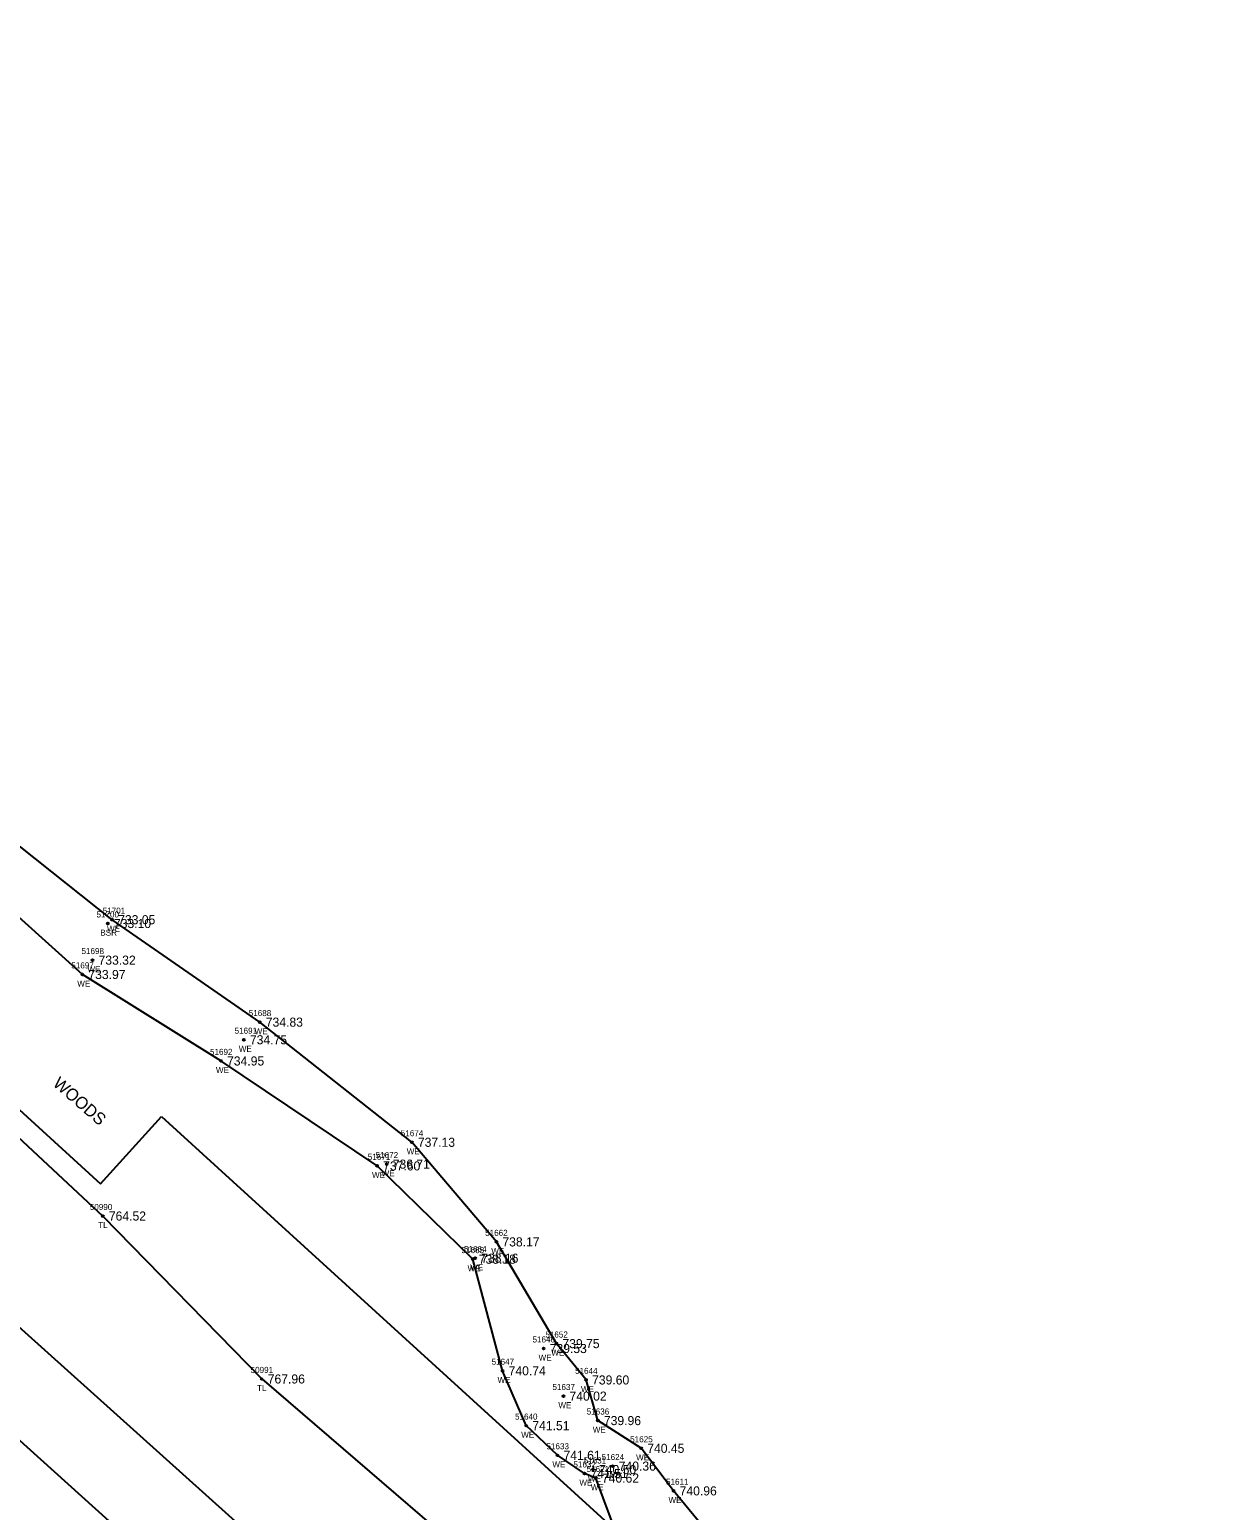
# Model space of a CAD drawing. Extents: x 1378245 to 1381654, y 996521 to 1000567.
# Drawn here: x 1379803.9 to 1379999.9, y 998853.4 to 999097.9 of the extents above; entities that cross this region are included whole.
import ezdxf

# ---------------------------------------------------------------- set-up
doc = ezdxf.new("R2010")
doc.units = 0
for name, color, linetype in [('RD_EX_H2O', 7, 'Continuous'), ('RD_EX_H2O_txCode', 7, 'Continuous'), ('RD_EX_Road', 7, 'Continuous'), ('RD_EX_RW', 7, 'Continuous'), ('RD_EX_SU_Elec', 7, 'Continuous'), ('RD_EX_TX_H2O_ELEV', 7, 'Continuous'), ('RD_EX_TX_VEG_ELEV', 7, 'Continuous'), ('RD_EX_VEG', 7, 'Continuous'), ('RD_EX_VEG_txCode', 7, 'Continuous'), ('RD_SMD_Locator', 7, 'Continuous'), ('RD_TX_Misc2', 7, 'Continuous')]:
    doc.layers.add(name, color=color, linetype=linetype)

msp = doc.modelspace()

# ---------------------------------------------------------------- linework, layer by layer
at = {"layer": 'RD_EX_H2O'}
for points in [[(1379918.79, 998846.24), (1379910.28, 998856.59), (1379904.93, 998863.62), (1379897.77, 998868.2), (1379895.82, 998874.91), (1379890.92, 998880.91), (1379881.01, 998897.71), (1379867.05, 998914.16), (1379841.93, 998934), (1379817.55, 998950.92), (1379777.38, 998982.83), (1379767.36, 998994.27), (1379764.43, 999001.11), (1379758.21, 999012.18), (1379756.79, 999014.96), (1379755.88, 999017.65), (1379756.7, 999019.63)], [(1379901.08, 998848.93), (1379897.44, 998858.7), (1379895.56, 998859.46), (1379891.1, 998862.46), (1379885.95, 998867.36), (1379882.04, 998876.42), (1379877.1, 998894.85), (1379861.31, 998910.26), (1379835.53, 998927.59), (1379812.63, 998941.87), (1379770.33, 998979.95), (1379755.35, 998994.63), (1379747.4, 999008), (1379729.37, 998999.6)]]:
    msp.add_lwpolyline(points, dxfattribs=at)
at = {"layer": 'RD_EX_Road'}
msp.add_lwpolyline([(1380011.64, 998674.46), (1379968.26, 998714.25), (1379924.81, 998753.18), (1379879.74, 998794.22), (1379836.83, 998833.73), (1379792.75, 998873.5), (1379756.46, 998907.13), (1379730.54, 998932.03)], dxfattribs=at)
at = {"layer": 'RD_EX_RW'}
for p, q in [((1379446.02, 999244.05), (1379815.63, 998907.31)), ((1379815.63, 998907.31), (1379825.73, 998918.4)), ((1379825.73, 998918.4), (1380047.49, 998716.36))]:
    msp.add_line(p, q, dxfattribs=at)
at = {"layer": 'RD_EX_SU_Elec'}
msp.add_lwpolyline([(1378514.25, 999944.12), (1378777.7, 999831.22), (1379190.17, 999461.05), (1379403.33, 999174.04), (1379756.94, 998924.25), (1380051.16, 998659.97), (1380327.91, 998390.65), (1380546.23, 998058.37)], dxfattribs=at)
at = {"layer": 'RD_EX_VEG'}
msp.add_lwpolyline([(1379745.61, 998947.42), (1379774.57, 998940.6), (1379816.01, 998901.98), (1379842.25, 998875.07), (1379890.91, 998833.28), (1379928.8, 998787.62), (1379978.22, 998752.26), (1380041.75, 998705.92), (1380067.2, 998663.35), (1380118.8, 998637.22), (1380159.3, 998606.26), (1380204.39, 998555.8), (1380215.44, 998549.46)], dxfattribs=at)
at = {"layer": 'RD_SMD_Locator'}
for centre in [(1379816.85, 998950.29), (1379817.55, 998950.92), (1379814.31, 998944.24), (1379812.63, 998941.87), (1379841.93, 998934), (1379839.31, 998931.09), (1379835.53, 998927.59), (1379867.05, 998914.16), (1379861.31, 998910.26), (1379862.89, 998910.55), (1379816.01, 998901.98), (1379881.01, 998897.71), (1379877.1, 998894.85), (1379877.52, 998895.02), (1379890.92, 998880.91), (1379888.82, 998880.1), (1379882.04, 998876.42), (1379842.25, 998875.07), (1379895.82, 998874.91), (1379892.09, 998872.24), (1379885.95, 998867.36), (1379897.77, 998868.2), (1379904.93, 998863.62), (1379891.1, 998862.46), (1379895.56, 998859.46), (1379896.97, 998860.11), (1379897.44, 998858.7), (1379900.22, 998860.68), (1379910.28, 998856.59)]:
    msp.add_circle(centre, 0.15, dxfattribs=at)

# ---------------------------------------------------------------- texts
at = {"layer": 'RD_EX_H2O_txCode'}
for s, p in [('51700', (1379814.97, 998951.29)), ('51701', (1379815.99, 998951.92)), ('BSR', (1379815.6, 998948.29)), ('WE', (1379816.71, 998948.92)), ('51698', (1379812.49, 998945.24)), ('51697', (1379810.81, 998942.87)), ('WE', (1379813.47, 998942.24)), ('WE', (1379811.79, 998939.87)), ('51688', (1379840.11, 998935)), ('51691', (1379837.77, 998932.09)), ('WE', (1379841.09, 998932)), ('WE', (1379838.47, 998929.09)), ('51692', (1379833.71, 998928.59)), ('WE', (1379834.69, 998925.59)), ('51674', (1379865.23, 998915.16)), ('51672', (1379861.07, 998911.55)), ('WE', (1379866.21, 998912.16)), ('51671', (1379859.77, 998911.26)), ('WE', (1379860.47, 998908.26)), ('WE', (1379862.05, 998908.55)), ('51662', (1379879.16, 998898.71)), ('51665', (1379875.26, 998895.85)), ('51664', (1379875.67, 998896.02)), ('WE', (1379880.17, 998895.71)), ('WE', (1379876.26, 998892.85)), ('WE', (1379876.68, 998893.02)), ('51646', (1379886.98, 998881.1)), ('51652', (1379889.1, 998881.91)), ('51647', (1379880.22, 998877.42)), ('WE', (1379887.98, 998878.1)), ('WE', (1379890.08, 998878.91)), ('51644', (1379894, 998875.91)), ('WE', (1379881.2, 998874.42)), ('51637', (1379890.27, 998873.24)), ('WE', (1379894.98, 998872.91)), ('WE', (1379891.25, 998870.24)), ('51640', (1379884.09, 998868.36)), ('51636', (1379895.93, 998869.2)), ('WE', (1379885.11, 998865.36)), ('WE', (1379896.93, 998866.2)), ('51633', (1379889.28, 998863.46)), ('51625', (1379903.11, 998864.62)), ('WE', (1379890.26, 998860.46)), ('51632', (1379893.74, 998860.46)), ('51631', (1379895.43, 998861.11)), ('51624', (1379898.4, 998861.68)), ('WE', (1379904.09, 998861.62)), ('51621', (1379895.91, 998859.7)), ('WE', (1379896.13, 998858.11)), ('WE', (1379899.38, 998858.68)), ('WE', (1379894.72, 998857.46)), ('WE', (1379896.6, 998856.7)), ('51611', (1379909.03, 998857.59)), ('WE', (1379909.44, 998854.59))]:
    msp.add_text(s, height=1, dxfattribs=at).set_placement(p)
at = {"layer": 'RD_EX_TX_H2O_ELEV'}
for s, p in [('733.05', (1379818.55, 998950.17)), ('733.10', (1379817.85, 998949.54)), ('733.32', (1379815.31, 998943.49)), ('733.97', (1379813.63, 998941.12)), ('734.83', (1379842.93, 998933.25)), ('734.75', (1379840.31, 998930.34)), ('734.95', (1379836.53, 998926.84)), ('737.13', (1379868.05, 998913.41)), ('737.60', (1379862.31, 998909.51)), ('736.71', (1379863.89, 998909.8)), ('738.17', (1379882.01, 998896.96)), ('738.18', (1379878.1, 998894.1)), ('738.16', (1379878.52, 998894.27)), ('739.53', (1379889.82, 998879.35)), ('739.75', (1379891.92, 998880.16)), ('740.74', (1379883.04, 998875.67)), ('739.60', (1379896.82, 998874.16)), ('740.02', (1379893.09, 998871.49)), ('739.96', (1379898.77, 998867.45)), ('741.51', (1379886.95, 998866.61)), ('740.45', (1379905.93, 998862.87)), ('741.61', (1379892.1, 998861.71)), ('740.36', (1379901.22, 998859.93)), ('741.51', (1379896.56, 998858.71)), ('740.50', (1379897.97, 998859.36)), ('740.62', (1379898.44, 998857.95)), ('740.96', (1379911.28, 998855.84))]:
    msp.add_text(s, height=1.5, dxfattribs=at).set_placement(p)
at = {"layer": 'RD_EX_TX_VEG_ELEV'}
for s, p in [('764.52', (1379817.01, 998901.23)), ('767.96', (1379843.25, 998874.32))]:
    msp.add_text(s, height=1.5, dxfattribs=at).set_placement(p)
at = {"layer": 'RD_EX_VEG_txCode'}
for s, p in [('50990', (1379813.86, 998902.98)), ('TL', (1379815.24, 998899.98)), ('50991', (1379840.42, 998876.07)), ('TL', (1379841.48, 998873.07))]:
    msp.add_text(s, height=1, dxfattribs=at).set_placement(p)
at = {"layer": 'RD_TX_Misc2'}
msp.add_text('WOODS', height=2, rotation=318.9261, dxfattribs=at).set_placement((1379807.62, 998923.63))

doc.saveas('drawing.dxf')
